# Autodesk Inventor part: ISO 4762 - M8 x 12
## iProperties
Comments: To add or edit properties for Autodesk Inventor files, use iProperties.
Created: 2004-08
Part Number: ISO 4762 - M8 x 12
Vendor: Autodesk Inc.
Document SubType Name: Modeling
Designer: John Blackburn
Material: Default
Description: Hexagon Socket Head Cap Screw
Standard: ISO 4762
Alert: To add or edit properties for Autodesk Inventor files, use iProperties.
Control State: 0
Master: False
Checked Out: False
Shininess: 64.0
Length Units: 11269
Angle Units: 11279
Time Units: 11290
Mass Units: 11283
Length Display Precision: 3
Angle Display Precision: 2
Compacted: True
EGR: 1
Density: 0.0
Volumn: 0.0
Area: 0.0
PropertySet Name: Model Information
Author: John Blackburn
Revision Number: 8
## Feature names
1. Body [Revolution]
2. Slot [Extrusion]
3. Fillet1
4. Chamfer1
